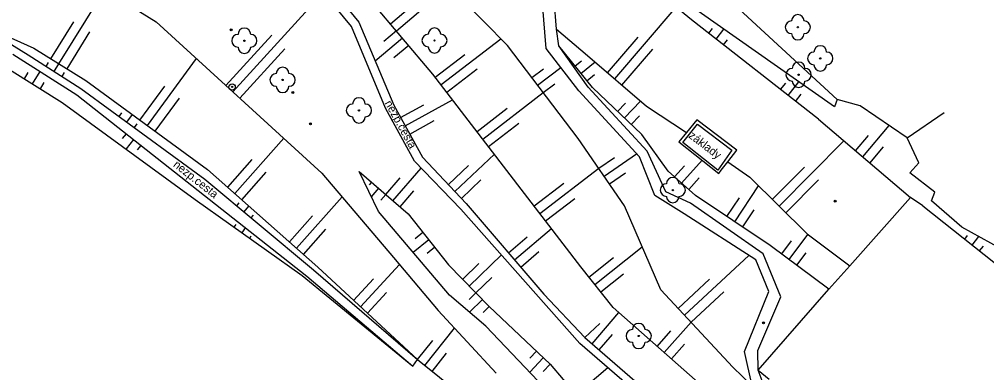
# Model space of a CAD drawing. Extents: x -639440 to -639026, y -1138850 to -1138262.
# Drawn here: x -639239.4 to -639162.7, y -1138684 to -1138656 of the extents above; entities that cross this region are included whole.
import ezdxf

# ---------------------------------------------------------------- set-up
doc = ezdxf.new("R2010")
doc.units = 0
for name, color, linetype in [('Vrstva 11', 7, 'Continuous'), ('Vrstva 14', 7, 'Continuous'), ('Vrstva 15', 7, 'Continuous'), ('Vrstva 20', 7, 'Continuous'), ('Vrstva 22', 7, 'Continuous'), ('Vrstva 25', 7, 'Continuous'), ('Vrstva 40', 7, 'Continuous'), ('Vrstva 7', 7, 'Continuous'), ('Vrstva 8', 7, 'Continuous')]:
    doc.layers.add(name, color=color, linetype=linetype)

msp = doc.modelspace()

# ---------------------------------------------------------------- linework, layer by layer
at = {"layer": 'Vrstva 11'}
for p, q in [((-639213.08, -1138656.54), (-639216.38, -1138652.5)), ((-639215.93, -1138651.95), (-639212.5, -1138656.19)), ((-639197.64, -1138658.27), (-639197.92, -1138654.72)), ((-639196.82, -1138656.76), (-639197, -1138654.41)), ((-639174.79, -1138662.91), (-639185.6, -1138655.32)), ((-639243.19, -1138656.03), (-639238.7, -1138658.79)), ((-639212.5, -1138656.19), (-639209.7, -1138662.78)), ((-639210.38, -1138663.02), (-639213.08, -1138656.54)), ((-639196.64, -1138658.08), (-639196.82, -1138656.76)), ((-639195.06, -1138661.64), (-639197.64, -1138658.27)), ((-639194.32, -1138661.34), (-639196.64, -1138658.08)), ((-639239.92, -1138658.74), (-639234.85, -1138661.95)), ((-639238.7, -1138658.79), (-639234.52, -1138661.45)), ((-639234.52, -1138661.45), (-639224.7, -1138668.63)), ((-639190.24, -1138666.86), (-639195.06, -1138661.64)), ((-639189.64, -1138666.41), (-639194.32, -1138661.34)), ((-639234.85, -1138661.95), (-639225.23, -1138669.53)), ((-639174.57, -1138662.33), (-639174.79, -1138662.91)), ((-639172.75, -1138662.82), (-639174.57, -1138662.33)), ((-639208.08, -1138667.2), (-639210.38, -1138663.02)), ((-639209.7, -1138662.78), (-639207.44, -1138666.9)), ((-639169.01, -1138665.36), (-639172.75, -1138662.82)), ((-639185.69, -1138663.93), (-639186.52, -1138664.93)), ((-639182.53, -1138666.33), (-639185.69, -1138663.93)), ((-639186.8, -1138665.72), (-639185.64, -1138664.27)), ((-639185.64, -1138664.27), (-639182.91, -1138666.35)), ((-639186.52, -1138664.93), (-639187.13, -1138665.68)), ((-639168.09, -1138667.35), (-639169.01, -1138665.36)), ((-639187.13, -1138665.68), (-639183.96, -1138668.18)), ((-639184.02, -1138667.91), (-639186.8, -1138665.72)), ((-639207.44, -1138666.9), (-639203.97, -1138670.56)), ((-639189.02, -1138669.94), (-639190.24, -1138666.86)), ((-639188.15, -1138669.65), (-639189.64, -1138666.41)), ((-639182.91, -1138666.35), (-639184.02, -1138667.91)), ((-639183.24, -1138667.25), (-639182.53, -1138666.33)), ((-639204.39, -1138671.01), (-639208.08, -1138667.2)), ((-639183.77, -1138667.93), (-639183.24, -1138667.25)), ((-639168.8, -1138668.14), (-639168.09, -1138667.35)), ((-639183.96, -1138668.18), (-639183.77, -1138667.93)), ((-639166.84, -1138669.66), (-639168.8, -1138668.14)), ((-639224.7, -1138668.63), (-639216.08, -1138675.82)), ((-639225.23, -1138669.53), (-639216.61, -1138676.33)), ((-639186.69, -1138671.39), (-639189.02, -1138669.94)), ((-639186.2, -1138670.55), (-639188.15, -1138669.65)), ((-639167.09, -1138670.36), (-639166.84, -1138669.66)), ((-639203.97, -1138670.56), (-639197.81, -1138677.76)), ((-639180.43, -1138674.54), (-639186.2, -1138670.55)), ((-639164.7, -1138672.44), (-639167.09, -1138670.36)), ((-639194.97, -1138681.67), (-639204.39, -1138671.01)), ((-639181.03, -1138675.02), (-639186.69, -1138671.39)), ((-639161.63, -1138674.12), (-639164.7, -1138672.44)), ((-639179.05, -1138677.96), (-639180.43, -1138674.54)), ((-639179.99, -1138677.55), (-639181.03, -1138675.02)), ((-639216.08, -1138675.82), (-639207.84, -1138682.93)), ((-639216.61, -1138676.33), (-639208.21, -1138683.45)), ((-639197.81, -1138677.76), (-639194.57, -1138681.19)), ((-639181.93, -1138682.29), (-639179.99, -1138677.55)), ((-639180.85, -1138682.2), (-639179.05, -1138677.96)), ((-639194.57, -1138681.19), (-639189.41, -1138685.64)), ((-639189.73, -1138686.16), (-639194.97, -1138681.67)), ((-639181.3, -1138685.01), (-639181.93, -1138682.29)), ((-639180.84, -1138683.76), (-639180.85, -1138682.2)), ((-639208.21, -1138683.45), (-639207.84, -1138682.93)), ((-639180.28, -1138685.26), (-639180.84, -1138683.76))]:
    msp.add_line(p, q, dxfattribs=at)
at = {"layer": 'Vrstva 14'}
for p, q in [((-639187.71, -1138650.18), (-639174.57, -1138662.33)), ((-639186.12, -1138656), (-639191.85, -1138651.33)), ((-639200.71, -1138658.05), (-639206.37, -1138652.27)), ((-639233.54, -1138653.07), (-639228.55, -1138656.16)), ((-639206.61, -1138660.31), (-639211.53, -1138654.5)), ((-639243.19, -1138656.03), (-639238.24, -1138658.26)), ((-639228.55, -1138656.16), (-639215.41, -1138668.15)), ((-639176.06, -1138663.89), (-639186.12, -1138656)), ((-639196.82, -1138656.76), (-639194.37, -1138658.83)), ((-639238.24, -1138658.26), (-639234.14, -1138660.81)), ((-639195.09, -1138665.41), (-639200.71, -1138658.05)), ((-639193.97, -1138661.37), (-639196.64, -1138658.08)), ((-639194.37, -1138658.83), (-639189.69, -1138662.85)), ((-639240.18, -1138659.94), (-639235.99, -1138662.55)), ((-639234.14, -1138660.81), (-639224.47, -1138667.86)), ((-639194.89, -1138675.58), (-639206.61, -1138660.31)), ((-639190.05, -1138665.1), (-639193.97, -1138661.37)), ((-639235.99, -1138662.55), (-639225.45, -1138670.25)), ((-639189.69, -1138662.85), (-639186.52, -1138664.93)), ((-639191.42, -1138670.75), (-639195.09, -1138665.41)), ((-639187.97, -1138668.01), (-639190.05, -1138665.1)), ((-639183.24, -1138667.25), (-639181.49, -1138668.48)), ((-639224.47, -1138667.86), (-639215.75, -1138675.6)), ((-639215.41, -1138668.15), (-639209.74, -1138674.83)), ((-639210.94, -1138671.2), (-639212.45, -1138668.03)), ((-639212.45, -1138668.03), (-639208.58, -1138671.39)), ((-639185.8, -1138669.94), (-639187.97, -1138668.01)), ((-639181.49, -1138668.48), (-639176.96, -1138672.98)), ((-639179.87, -1138673.88), (-639185.8, -1138669.94)), ((-639225.45, -1138670.25), (-639216.98, -1138676.26)), ((-639188.55, -1138677.4), (-639191.42, -1138670.75)), ((-639205.29, -1138677.82), (-639210.94, -1138671.2)), ((-639208.58, -1138671.39), (-639205.37, -1138675.42)), ((-639176.96, -1138672.98), (-639173.58, -1138675.51)), ((-639175.22, -1138677.36), (-639179.87, -1138673.88)), ((-639209.74, -1138674.83), (-639206.21, -1138679.03)), ((-639205.37, -1138675.42), (-639202.16, -1138678.72)), ((-639216.98, -1138676.26), (-639208.21, -1138683.45)), ((-639215.75, -1138675.6), (-639207.84, -1138682.93)), ((-639192.33, -1138678.81), (-639194.89, -1138675.58)), ((-639202.41, -1138680.28), (-639205.29, -1138677.82)), ((-639182.85, -1138683.52), (-639188.55, -1138677.4)), ((-639206.21, -1138679.03), (-639201.59, -1138684.01)), ((-639202.16, -1138678.72), (-639197.32, -1138683.3)), ((-639179.56, -1138690.05), (-639192.33, -1138678.81)), ((-639183, -1138700.67), (-639202.41, -1138680.28)), ((-639207.84, -1138682.93), (-639183.7, -1138702.12)), ((-639197.32, -1138683.3), (-639190.27, -1138691.56)), ((-639181.3, -1138685.01), (-639182.85, -1138683.52))]:
    msp.add_line(p, q, dxfattribs=at)
at = {"layer": 'Vrstva 15'}
for p, q in [((-639209.99, -1138656.318), (-639205.844, -1138652.807)), ((-639236.256, -1138659.494), (-639232.616, -1138653.642)), ((-639222.47, -1138661.708), (-639215.288, -1138653.837)), ((-639209.506, -1138656.89), (-639207.412, -1138655.117)), ((-639192.202, -1138660.692), (-639187.327, -1138655.016)), ((-639236.892, -1138659.098), (-639235.073, -1138656.173)), ((-639235.619, -1138659.89), (-639233.798, -1138656.964)), ((-639209.506, -1138656.89), (-639210.497, -1138657.73)), ((-639184.751, -1138657.074), (-639184.458, -1138656.701)), ((-639184.161, -1138657.537), (-639183.551, -1138656.759)), ((-639223.024, -1138661.203), (-639219.396, -1138657.226)), ((-639209.021, -1138657.463), (-639211.182, -1138659.292)), ((-639205.971, -1138661.142), (-639201.239, -1138657.51)), ((-639192.771, -1138660.203), (-639190.34, -1138657.373)), ((-639183.571, -1138657.999), (-639183.253, -1138657.595)), ((-639221.916, -1138662.214), (-639218.362, -1138658.319)), ((-639208.537, -1138658.035), (-639209.706, -1138659.025)), ((-639191.633, -1138661.181), (-639189.189, -1138658.335)), ((-639237.274, -1138659.698), (-639237.083, -1138659.398)), ((-639229.228, -1138664.391), (-639225.353, -1138659.077)), ((-639206.428, -1138660.547), (-639204.098, -1138658.759)), ((-639195.35, -1138659.669), (-639194.847, -1138659.261)), ((-639194.878, -1138660.252), (-639193.766, -1138659.349)), ((-639238.361, -1138661.073), (-639237.76, -1138660.108)), ((-639236.641, -1138660.1), (-639236.255, -1138659.494)), ((-639205.515, -1138661.737), (-639203.112, -1138659.894)), ((-639198.775, -1138660.584), (-639197.858, -1138659.884)), ((-639198.32, -1138661.18), (-639196.485, -1138659.779)), ((-639238.998, -1138660.677), (-639238.695, -1138660.192)), ((-639236.008, -1138660.503), (-639235.813, -1138660.197)), ((-639194.405, -1138660.834), (-639193.796, -1138660.34)), ((-639178.461, -1138662.007), (-639177.614, -1138660.927)), ((-639237.724, -1138661.47), (-639237.425, -1138660.989)), ((-639229.834, -1138663.949), (-639227.872, -1138661.259)), ((-639197.865, -1138661.776), (-639196.947, -1138661.075)), ((-639179.051, -1138661.544), (-639178.64, -1138661.02)), ((-639228.622, -1138664.833), (-639226.709, -1138662.209)), ((-639208.811, -1138664.401), (-639205.053, -1138662.339)), ((-639202.66, -1138665.457), (-639197.864, -1138661.777)), ((-639191.433, -1138663.784), (-639190.16, -1138662.446)), ((-639177.871, -1138662.47), (-639177.435, -1138661.914)), ((-639209.172, -1138663.743), (-639207.343, -1138662.74)), ((-639203.116, -1138664.862), (-639200.718, -1138663.021)), ((-639191.977, -1138663.267), (-639191.353, -1138662.612)), ((-639231.486, -1138663.669), (-639231.265, -1138663.367)), ((-639230.88, -1138664.111), (-639230.439, -1138663.508)), ((-639208.45, -1138665.058), (-639206.52, -1138664)), ((-639190.89, -1138664.301), (-639190.234, -1138663.612)), ((-639230.275, -1138664.554), (-639230.054, -1138664.252)), ((-639202.203, -1138666.052), (-639199.806, -1138664.212)), ((-639172.543, -1138666.873), (-639170.438, -1138664.39)), ((-639230.938, -1138665.033), (-639231.24, -1138665.416)), ((-639230.349, -1138665.497), (-639230.936, -1138666.242)), ((-639222.321, -1138669.767), (-639218.435, -1138665.389)), ((-639173.115, -1138666.387), (-639172.089, -1138665.177)), ((-639229.76, -1138665.961), (-639230.045, -1138666.323)), ((-639179.18, -1138670.775), (-639174.042, -1138665.602)), ((-639171.972, -1138667.358), (-639170.893, -1138666.086)), ((-639222.882, -1138669.269), (-639220.936, -1138667.077)), ((-639204.869, -1138669.612), (-639201.744, -1138666.65)), ((-639193.468, -1138667.77), (-639192.224, -1138666.915)), ((-639193.043, -1138668.388), (-639190.465, -1138666.616)), ((-639209.784, -1138670.345), (-639207.539, -1138667.759)), ((-639205.385, -1138669.068), (-639203.794, -1138667.56)), ((-639198.135, -1138671.353), (-639193.468, -1138667.771)), ((-639187.461, -1138668.462), (-639186.666, -1138667.568)), ((-639186.901, -1138668.961), (-639185.28, -1138667.139)), ((-639179.712, -1138670.246), (-639177.164, -1138667.681)), ((-639221.76, -1138670.265), (-639219.821, -1138668.08)), ((-639210.35, -1138669.853), (-639209.206, -1138668.536)), ((-639192.618, -1138669.006), (-639191.35, -1138668.134)), ((-639186.341, -1138669.459), (-639185.515, -1138668.532)), ((-639211.483, -1138668.869), (-639211.666, -1138669.08)), ((-639210.917, -1138669.361), (-639211.498, -1138670.029)), ((-639204.353, -1138670.156), (-639202.819, -1138668.702)), ((-639198.591, -1138670.758), (-639196.242, -1138668.955)), ((-639182.685, -1138672.009), (-639180.797, -1138669.168)), ((-639178.648, -1138671.303), (-639176.058, -1138668.696)), ((-639217.432, -1138674.107), (-639213.814, -1138670.03)), ((-639210.351, -1138669.853), (-639210.748, -1138670.31)), ((-639209.217, -1138670.837), (-639208.116, -1138669.568)), ((-639183.31, -1138671.594), (-639182.325, -1138670.112)), ((-639222.162, -1138670.747), (-639221.961, -1138670.506)), ((-639221.586, -1138671.227), (-639221.199, -1138670.763)), ((-639197.678, -1138671.948), (-639195.36, -1138670.169)), ((-639221.01, -1138671.708), (-639220.824, -1138671.485)), ((-639217.993, -1138673.609), (-639216.149, -1138671.531)), ((-639182.061, -1138672.425), (-639181.158, -1138671.066)), ((-639222.359, -1138672.443), (-639222.212, -1138672.235)), ((-639221.748, -1138672.877), (-639221.475, -1138672.492)), ((-639221.136, -1138673.311), (-639221.011, -1138673.134)), ((-639216.872, -1138674.605), (-639215.098, -1138672.606)), ((-639207.406, -1138672.864), (-639208.035, -1138673.365)), ((-639200.626, -1138674.469), (-639199.152, -1138673.208)), ((-639200.138, -1138675.039), (-639197.221, -1138672.543)), ((-639178.366, -1138675.006), (-639176.889, -1138673.033)), ((-639164.454, -1138673.391), (-639164.228, -1138673.106)), ((-639163.866, -1138673.857), (-639163.335, -1138673.187)), ((-639206.939, -1138673.45), (-639208.177, -1138674.437)), ((-639178.966, -1138674.556), (-639178.2, -1138673.533)), ((-639163.278, -1138674.322), (-639162.973, -1138673.937)), ((-639206.472, -1138674.037), (-639207.081, -1138674.522)), ((-639203.729, -1138677.107), (-639201.187, -1138674.635)), ((-639199.651, -1138675.608), (-639198.207, -1138674.373)), ((-639193.783, -1138676.976), (-639190.02, -1138673.993)), ((-639186.667, -1138679.422), (-639181.569, -1138674.674)), ((-639177.765, -1138675.455), (-639177.027, -1138674.469)), ((-639212.35, -1138678.75), (-639209.254, -1138675.409)), ((-639204.252, -1138676.57), (-639202.968, -1138675.321)), ((-639194.249, -1138676.388), (-639192.289, -1138674.834)), ((-639193.318, -1138677.564), (-639191.515, -1138676.135)), ((-639212.9, -1138678.241), (-639211.32, -1138676.535)), ((-639203.206, -1138677.645), (-639201.948, -1138676.421)), ((-639187.178, -1138678.873), (-639184.699, -1138676.565)), ((-639211.8, -1138679.26), (-639210.284, -1138677.624)), ((-639203.206, -1138677.645), (-639203.741, -1138678.165)), ((-639186.156, -1138679.971), (-639183.566, -1138677.56)), ((-639202.683, -1138678.182), (-639203.704, -1138679.175)), ((-639202.16, -1138678.72), (-639202.645, -1138679.192)), ((-639194.003, -1138681.679), (-639191.874, -1138679.211)), ((-639194.571, -1138681.189), (-639193.378, -1138680.063)), ((-639188.275, -1138682.379), (-639186.155, -1138679.971)), ((-639207.253, -1138683.397), (-639204.902, -1138680.44)), ((-639188.838, -1138681.884), (-639187.754, -1138680.652)), ((-639207.84, -1138682.93), (-639206.629, -1138681.407)), ((-639193.435, -1138682.169), (-639192.373, -1138680.938)), ((-639198.41, -1138682.269), (-639198.935, -1138682.824)), ((-639187.712, -1138682.875), (-639186.677, -1138681.699)), ((-639206.666, -1138683.863), (-639205.526, -1138682.43)), ((-639197.865, -1138682.785), (-639198.942, -1138683.923)), ((-639197.32, -1138683.3), (-639197.872, -1138683.883)), ((-639195.27, -1138685.701), (-639192.763, -1138683.561))]:
    msp.add_line(p, q, dxfattribs=at)
at = {"layer": 'Vrstva 20'}
for centre, radius in [((-639222.6, -1138656.8), 0.075), ((-639222.6, -1138656.8), 0.0204), ((-639217.72, -1138661.76), 0.075), ((-639217.72, -1138661.76), 0.0204), ((-639216.33, -1138664.25), 0.075), ((-639216.33, -1138664.25), 0.0204), ((-639174.73, -1138670.38), 0.075), ((-639174.73, -1138670.38), 0.0204), ((-639180.41, -1138680.02), 0.075), ((-639180.41, -1138680.02), 0.0204)]:
    msp.add_circle(centre, radius, dxfattribs=at)
at = {"layer": 'Vrstva 22'}
for centre in [(-639177.69, -1138656.6), (-639221.56, -1138657.67), (-639206.49, -1138657.65), (-639175.91, -1138659.07), (-639218.53, -1138660.77), (-639177.63, -1138660.36), (-639212.48, -1138663.19), (-639187.6, -1138669.5), (-639190.3, -1138681.06)]:
    msp.add_circle(centre, 0.05, dxfattribs=at)
for centre, start, end in [((-639178.19, -1138656.6), 90, 270), ((-639177.69, -1138656.1), 0, 180), ((-639177.19, -1138656.6), 270, 90), ((-639221.56, -1138657.17), 0, 180), ((-639206.49, -1138657.15), 0, 180), ((-639177.69, -1138657.1), 180, 0), ((-639222.06, -1138657.67), 90, 270), ((-639221.06, -1138657.67), 270, 90), ((-639206.99, -1138657.65), 90, 270), ((-639205.99, -1138657.65), 270, 90), ((-639221.56, -1138658.17), 180, 0), ((-639206.49, -1138658.15), 180, 0), ((-639176.41, -1138659.07), 90, 270), ((-639175.91, -1138658.57), 0, 180), ((-639175.41, -1138659.07), 270, 90), ((-639177.63, -1138659.86), 0, 180), ((-639218.53, -1138660.27), 0, 180), ((-639178.13, -1138660.36), 90, 270), ((-639177.13, -1138660.36), 270, 90), ((-639175.91, -1138659.57), 180, 0), ((-639219.03, -1138660.77), 90, 270), ((-639218.03, -1138660.77), 270, 90), ((-639177.63, -1138660.86), 180, 0), ((-639218.53, -1138661.27), 180, 0), ((-639212.48, -1138662.69), 0, 180), ((-639212.98, -1138663.19), 90, 270), ((-639211.98, -1138663.19), 270, 90), ((-639212.48, -1138663.69), 180, 0), ((-639187.6, -1138669), 0, 180), ((-639188.1, -1138669.5), 90, 270), ((-639187.1, -1138669.5), 270, 90), ((-639187.6, -1138670), 180, 0), ((-639190.3, -1138680.56), 0, 180), ((-639190.8, -1138681.06), 90, 270), ((-639189.8, -1138681.06), 270, 90), ((-639190.3, -1138681.56), 180, 0)]:
    msp.add_arc(centre, 0.5, start, end, dxfattribs=at)
at = {"layer": 'Vrstva 25'}
for radius in [0.25, 0.05]:
    msp.add_circle((-639222.53, -1138661.33), radius, dxfattribs=at)
at = {"layer": 'Vrstva 7'}
for p, q in [((-639176.06, -1138663.89), (-639168.75, -1138670.09)), ((-639169.01, -1138665.36), (-639166.08, -1138663.36)), ((-639173.58, -1138675.51), (-639168.75, -1138670.09)), ((-639167.79, -1138670.75), (-639161.26, -1138675.92)), ((-639175.22, -1138677.36), (-639173.58, -1138675.51)), ((-639180.84, -1138683.76), (-639175.22, -1138677.36))]:
    msp.add_line(p, q, dxfattribs=at)
at = {"layer": 'Vrstva 8'}
for p, q in [((-639167.79, -1138670.75), (-639168.75, -1138670.09)), ((-639180.84, -1138683.76), (-639179.96, -1138684.47))]:
    msp.add_line(p, q, dxfattribs=at)

# ---------------------------------------------------------------- texts
at = {"layer": 'Vrstva 40'}
for s, rotation, p in [('nezp.cesta', 298.82132, (-639210.459, -1138662.603)), ('základy', 322.53736, (-639186.402, -1138665.292)), ('nezp.cesta', 321.76395, (-639227.253, -1138667.59))]:
    msp.add_text(s, height=0.65, rotation=rotation, dxfattribs=at).set_placement(p)

doc.saveas('drawing.dxf')
